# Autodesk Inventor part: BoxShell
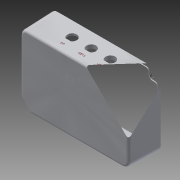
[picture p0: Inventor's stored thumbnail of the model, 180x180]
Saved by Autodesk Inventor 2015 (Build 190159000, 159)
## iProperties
Created: 2014-07
Part Number: BoxShell
Material: Aluminum 6061
Document SubType Name: Modeling
Designer: Gavin
Density: 2.7 g/cm^3
Appearance: White
Author: Gavin
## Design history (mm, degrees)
node "Blocks"
  sketch "Cutout1"
    geometry: L1 (34.559, -37.41)-(46.559, -37.41); A1 r 10 centre (40.559, -29.41) between (46.559, -37.41) and (34.559, -37.41); 2 further points
    constraints: 2 coincident, 2 end point, 2 point on circle, 1 centre point, 1 horizontal
    dimensions: "d16" = 20 diameter of A1; "d17" = 18 dimension on A1 L1
derived "BoxSketch.ipt"
  sketch "Sketch1"
    geometry: L1 (-135, -69.5)-(-139, -69.5) reference; L2 (-147.5, -61)-(-147.5, 61) reference; L3 (-139, 69.5)-(-135, 69.5) reference; L4 (-129.5, 75)-(-129.5, 79) reference; L5 (-121, 87.5)-(121, 87.5) reference; L6 (129.5, 79)-(129.5, 75) reference; L7 (135, 69.5)-(139, 69.5) reference; L8 (147.5, 61)-(147.5, -61) reference; L9 (139, -69.5)-(135, -69.5) reference; L10 (129.5, -75)-(129.5, -79) reference; L11 (121, -82)-(-121, -82) reference; L12 (-142, -61)-(-142, 61) reference; L13 (-121, 82)-(121, 82) reference; L14 (142, 61)-(142, -61) reference; L15 (124, -79)-(124, -75) reference; L16 (135, -64)-(139, -64) reference; L17 (0, -90)-(0, 90) reference; L18 (150, 0)-(-150, 0) reference; L19 (-124, -79)-(-124, -75) reference; L20 (-135, -64)-(-139, -64) reference; L21 (124, 79)-(124, 75) reference; L22 (135, 64)-(139, 64) reference; L23 (-124, 79)-(-124, 75) reference; L24 (-135, 64)-(-139, 64) reference; L25 (-121, -84.5)-(121, -84.5) reference; L26 (126.5, -79)-(126.5, -75) reference; L27 (135, -66.5)-(139, -66.5) reference; L28 (144.5, -61)-(144.5, 61) reference; L29 (139, 66.5)-(135, 66.5) reference; L30 (126.5, 75)-(126.5, 79) reference; L31 (121, 84.5)-(-121, 84.5) reference; L32 (-126.5, 79)-(-126.5, 75) reference; L33 (-135, 66.5)-(-139, 66.5) reference; L34 (-144.5, 61)-(-144.5, -61) reference; L35 (-139, -66.5)-(-135, -66.5) reference; L36 (-126.5, -75)-(-126.5, -79) reference; L37 (121, -87.5)-(-121, -87.5) reference; L38 (-129.5, -79)-(-129.5, -75) reference; L39 (135, 90)-(-135, 90) reference; L40 (-150, 75)-(-150, -75) reference; L41 (-135, -90)-(135, -90) reference; L42 (150, -75)-(150, 75) reference; L43 (150, 90)-(-150, -90) reference; L44 (-150, 90)-(150, -90) reference; C1 r 3 at (135, -75) reference; C2 r 3 at (-135, -75) reference; C3 r 3 at (135, 75) reference; C4 r 3 at (-135, 75) reference; A1 r 8.5 centre (-139, -61) between (-147.5, -61) and (-139, -69.5) reference; A2 r 8.5 centre (-139, 61) between (-139, 69.5) and (-147.5, 61) reference; A3 r 5.5 centre (-135, 75) between (-135, 69.5) and (-129.5, 75) reference; A4 r 8.5 centre (-121, 79) between (-121, 87.5) and (-129.5, 79) reference; A5 r 8.5 centre (121, 79) between (129.5, 79) and (121, 87.5) reference; A6 r 5.5 centre (135, 75) between (129.5, 75) and (135, 69.5) reference; A7 r 8.5 centre (139, 61) between (147.5, 61) and (139, 69.5) reference; A8 r 8.5 centre (139, -61) between (139, -69.5) and (147.5, -61) reference; A9 r 5.5 centre (135, -75) between (135, -69.5) and (129.5, -75) reference; A10 r 8.5 centre (121, -79) between (121, -87.5) and (129.5, -79) reference; A11 r 15 centre (-135, 75) between (-135, 90) and (-150, 75) reference; A12 r 11 centre (135, -75) between (135, -64) and (124, -75) reference; A13 r 3 centre (121, -79) between (121, -82) and (124, -79) reference; A14 r 3 centre (139, -61) between (139, -64) and (142, -61) reference; A15 r 11 centre (-135, -75) between (-124, -75) and (-135, -64) reference; A16 r 3 centre (-121, -79) between (-124, -79) and (-121, -82) reference; A17 r 3 centre (-139, -61) between (-142, -61) and (-139, -64) reference; A18 r 11 centre (135, 75) between (124, 75) and (135, 64) reference; A19 r 3 centre (121, 79) between (124, 79) and (121, 82) reference; A20 r 3 centre (139, 61) between (142, 61) and (139, 64) reference; A21 r 3 centre (-121, 79) between (-121, 82) and (-124, 79) reference; A22 r 11 centre (-135, 75) between (-135, 64) and (-124, 75) reference; A23 r 3 centre (-139, 61) between (-139, 64) and (-142, 61) reference; A24 r 5.5 centre (121, -79) between (121, -84.5) and (126.5, -79) reference; A25 r 8.5 centre (135, -75) between (135, -66.5) and (126.5, -75) reference; A26 r 5.5 centre (139, -61) between (139, -66.5) and (144.5, -61) reference; A27 r 5.5 centre (139, 61) between (144.5, 61) and (139, 66.5) reference; A28 r 8.5 centre (135, 75) between (126.5, 75) and (135, 66.5) reference; A29 r 5.5 centre (121, 79) between (126.5, 79) and (121, 84.5) reference; A30 r 5.5 centre (-121, 79) between (-121, 84.5) and (-126.5, 79) reference; A31 r 8.5 centre (-135, 75) between (-135, 66.5) and (-126.5, 75) reference; A32 r 5.5 centre (-139, 61) between (-139, 66.5) and (-144.5, 61) reference; A33 r 5.5 centre (-139, -61) between (-144.5, -61) and (-139, -66.5) reference; A34 r 8.5 centre (-135, -75) between (-126.5, -75) and (-135, -66.5) reference; A35 r 5.5 centre (-121, -79) between (-126.5, -79) and (-121, -84.5) reference; A36 r 8.5 centre (-121, -79) between (-129.5, -79) and (-121, -87.5) reference; A37 r 5.5 centre (-135, -75) between (-129.5, -75) and (-135, -69.5) reference; A38 r 15 centre (135, -75) between (135, -90) and (150, -75) reference; A39 r 15 centre (-135, -75) between (-150, -75) and (-135, -90) reference; A40 r 15 centre (135, 75) between (150, 75) and (135, 90) reference; 1 further point
extrude "Extrusion1" new body sketch "Sketch1" taper "d2" = -2 deg; distance "Depth" = 65
fillet "Fillet1" dims "d3" = 5
extrude "Extrusion2" cut sketch "Sketch1" distance "d4" = 60 (computed from Depth); taper "d5" = -2 deg
fillet "Fillet2" dims "d6" = 2
extrude "Extrusion3" cut sketch "Sketch1" distance "d7" = 2; taper "d8" = 0 deg
hole "Hole1" sketch "Sketch1" diameter "d9" = 6.647; stored, may be unused: countersink angle "d13" = 90 deg, drill point angle "d15" = 118 deg; dims "d10" = 20, "d11" = 4, "d12" = 2, "d14" = 26.2
sketch "Sketch2"
  geometry: L1 (135, 14.248)-(135, -85.491) reference; L2 (270, 0)-(0, 0) reference; L3 (95, -30)-(175, -30); 2 further points
  constraints: 2 end point, 2 horizontal, 1 midpoint, 1 point on line, 1 other
  dimensions: "d18" = 40 dimension on L1; "d19" = 30 dimension on L2
extrude "Extrusion4" cut sketch "Sketch2" distance "d20" = 10; taper "d21" = 0 deg
sketch "Sketch3"
  geometry: C1 r 14.744 at (161, -29.721); 2 further points
  constraints: 1 centre point, 1 coincident
extrude "Extrusion5" cut sketch "Sketch3" distance "d22" = 4; taper "d23" = 0 deg
sketch "Sketch4"
  geometry: L1 (91.5, -48)-(98.5, -48); L2 (98.5, -48)-(98.5, -53); L3 (98.5, -53)-(91.5, -53); L4 (91.5, -53)-(91.5, -48); L5 (101, -38)-(89, -38) reference; L6 (95, -38)-(95, -48); L7 (101, -38)-(89, -38) reference; 3 further points
  constraints: 2 end point, 2 midpoint, 2 perpendicular, 2 other
  dimensions: "d24" = 7 distance of L1.start L1.end; "d25" = 5 distance of L1.end L2.end; "d26" = 10 distance between parallel lines of L5 L1
extrude "IOEngrave" cut sketch "Sketch4" distance "d27" = 0.3; taper "d28" = 0 deg
sketch "Sketch5" dims "d29" = 40
  geometry: L1 (135, 14.248)-(135, -85.491) reference; L2 (95, -30)-(175, -30) reference; 1 further point
  constraints: 1 horizontal, 1 other
extrude "ComCutouts" cut sketch "Sketch5" distance "d30" = 10; taper "d31" = 0 deg
sketch "Sketch6"
  geometry: L1 (141, -38)-(129, -38) reference; L2 (181, -38)-(169, -38) reference; L3 (128, -48)-(142, -48); L4 (142, -48)-(142, -51.5); L5 (142, -51.5)-(128, -51.5); L6 (128, -51.5)-(128, -48); L7 (168, -51.5)-(168, -48); L8 (168, -48)-(182, -48); L9 (182, -48)-(182, -51.5); L10 (182, -51.5)-(168, -51.5); A1 r 10 centre (135, -30) between (141, -38) and (129, -38) reference; A2 r 10 centre (175, -30) between (181, -38) and (169, -38) reference; 4 further points
  constraints: 2 equal length, 2 midpoint, 2 vertical alignment, 1 collinear, 4 other
  dimensions: "d32" = 14 distance of L3.start L3.end; "d33" = 3.5 distance of L3.end L4.end; "d34" = 10 distance between parallel lines of L3 L1
extrude "ComEngrave" cut sketch "Sketch6" distance "d35" = 0.3; taper "d36" = 0 deg
body "Solid1"
node "Cutout1:1" dims "d18" = 40, "d19" = 30
node "Cutout1:2" dims "d29" = 40
node "Cutout1:3" dims "d29" = 40
